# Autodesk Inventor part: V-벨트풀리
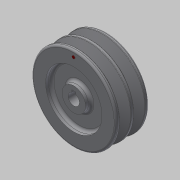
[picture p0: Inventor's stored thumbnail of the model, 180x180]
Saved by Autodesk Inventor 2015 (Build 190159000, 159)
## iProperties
Created: 2016-08
Part Number: V-벨트풀리
Material: 알루미늄 6061
Document SubType Name: Modeling
Designer: mduedu
Density: 2.71 g/cm^3
Appearance: 기본값
Author: mduedu
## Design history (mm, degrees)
sketch "스케치1"
  geometry: L1 (0, 17.5)-(0, -17.5); L2 (0, -17.5)-(45, -17.5); L3 (45, -17.5)-(45, 17.5); L4 (45, 17.5)-(0, 17.5); L5 (45, -1.524)-(32.5, -5.346); L6 (32.5, -5.346)-(32.5, -9.654); L7 (32.5, -9.654)-(45, -13.476); L8 (45, 13.476)-(32.5, 9.654); L9 (32.5, 9.654)-(32.5, 5.346); L10 (32.5, 5.346)-(45, 1.524); L11 (40.5, 17.5)-(40.5, -17.5); L12 (45, -7.5)-(0, -7.5); L13 (45, 7.5)-(0, 7.5); 8 further points
  constraints: 26 end point, 20 point on line, 6 perpendicular, 3 equal length, 3 midpoint, 2 collinear, 1 coincident, 1 horizontal, 1 vertical
  dimensions: "d43" = 90 diameter of L3 L1; "d45" = 34 deg angle of L7 L5; "d47" = 34 deg angle of L8 L10; "d49" = 9.2 distance of point (40.5, -12.1) point (40.5, -2.9); "d50" = 9.2 distance of point (40.5, 12.1) point (40.5, 2.9) (derived); "d51" = 10 distance between parallel lines of L12 L2; "d52" = 10 distance between parallel lines of L13 L4; "d53" = 15 distance between parallel lines of L12 L13; "d54" = 4.5 distance between parallel lines of L11 L3; "d55" = 8 distance between parallel lines of L6 L11
revolve "회전1" sketch "스케치1" stored, may be unused: angle "d8" = 90 deg
sketch "스케치2"
  geometry: L1 (-2, 0)-(2, 0); L2 (2, 0)-(2, 7.8); L3 (2, 7.8)-(-2, 7.8); L4 (-2, 7.8)-(-2, 0); C1 r 6 at (0, 0); 3 further points
  constraints: 8 end point, 3 coincident, 2 parallel, 1 centre point, 1 horizontal, 1 midpoint, 1 perpendicular
  dimensions: "d9" = 12 diameter of C1; "d11" = 4 distance of L2.end L3.end; "d12" = 7.8 distance of L1.end L2.end
extrude "돌출1" cut sketch "스케치2" stored distance "d13" = 10; taper "d14" = 0 deg
sketch "스케치4"
  geometry: C1 r 30 at (0, 0); C2 r 12.5 at (0, 0); 2 further points
  constraints: 3 coincident, 2 centre point
  dimensions: "d30" = 60 diameter of C1; "d31" = 25 diameter of C2
extrude "돌출2" cut sketch "스케치4" distance "d32" = 6; taper "d33" = 0 deg
fillet "모깎기6" dims "d34" = 3
fillet "모깎기8" dims "d56" = 0.5, "d57" = 1, "d58" = 2
chamfer "모따기1" distance "d26" = 0.5; stored, may be unused: second distance "d27" = 2, angle "d28" = 45 deg
sketch "스케치5" dims "d38" = 78
  geometry: C1 r 1.5 at (0, 39); 3 further points
  constraints: 2 coincident, 2 vertical alignment, 1 centre point, 2 other
  dimensions: "d40" = 3 diameter of C1
extrude "돌출3" join sketch "스케치5" distance "d41" = 0.5; taper "d42" = 0 deg
node "솔리드1"
mirror "대칭2"
